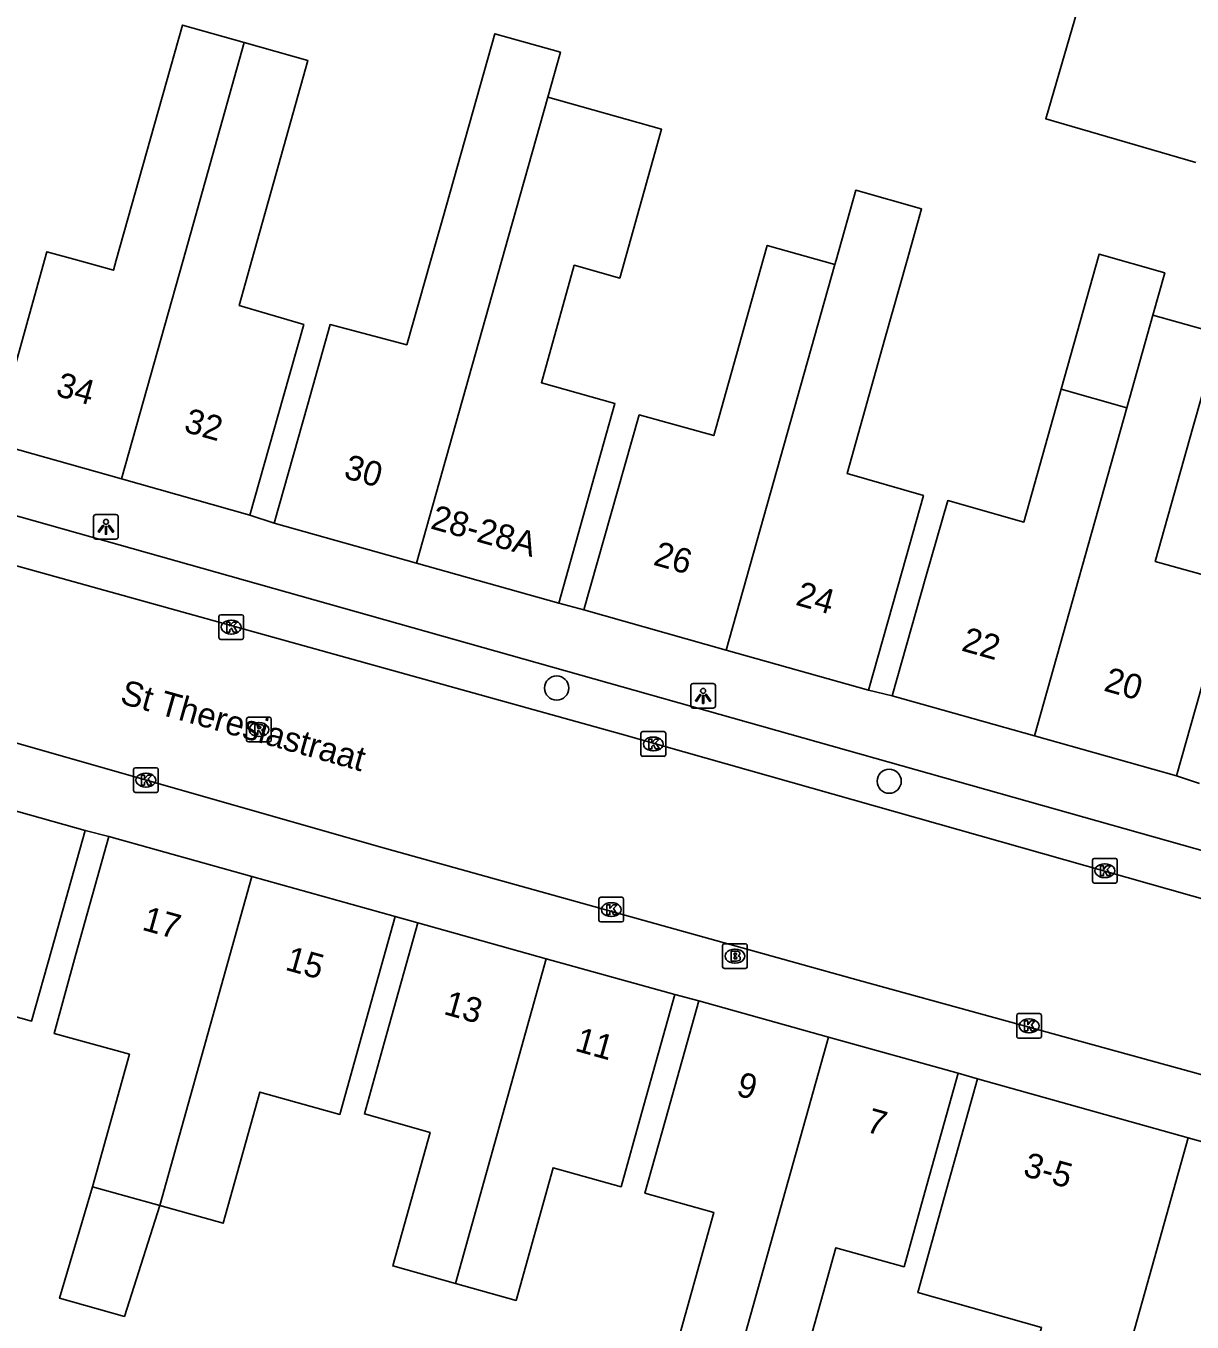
# Model space of a CAD drawing. Extents: x 158087 to 159494, y 382905 to 383981.
# Drawn here: x 158768.8 to 158816, y 383207 to 383259.5 of the extents above; entities that cross this region are included whole.
import ezdxf

# ---------------------------------------------------------------- set-up
doc = ezdxf.new("R2010")
doc.units = 0
for name, color, linetype in [('IMGEO_Boom', 7, 'Continuous'), ('IMGEO_Brandkraan', 7, 'Continuous'), ('IMGEO_Kolk', 7, 'Continuous'), ('IMGEO_Lichtpunt', 7, 'Continuous'), ('IMGEO_Openbare_ruimte_label', 7, 'Continuous'), ('IMGEO_Pand', 7, 'Continuous'), ('IMGEO_Pand_nummerreeks', 7, 'Continuous'), ('IMGEO_Rijbaan_lokaal_open', 7, 'Continuous'), ('IMGEO_Rioolput', 7, 'Continuous'), ('IMGEO_Voetpad_open', 7, 'Continuous')]:
    doc.layers.add(name, color=color, linetype=linetype)

msp = doc.modelspace()

# ---------------------------------------------------------------- linework, layer by layer
at = {"layer": 'IMGEO_Boom'}
for centre in [(158790.32, 383232.685), (158803.776, 383228.915)]:
    msp.add_circle(centre, 0.489, dxfattribs=at)
at = {"layer": 'IMGEO_Brandkraan'}
for p, q in [((158797.109, 383222.337), (158797.961, 383222.337)), ((158797.034, 383221.411), (158797.034, 383222.263)), ((158797.522, 383222.117), (158797.547, 383222.117)), ((158798.035, 383222.263), (158798.035, 383221.411)), ((158797.961, 383221.337), (158797.109, 383221.337)), ((158797.545, 383221.557), (158797.52, 383221.557))]:
    msp.add_line(p, q, dxfattribs=at)
for points in [[(158797.109, 383222.337), (158797.961, 383222.337)], [(158797.034, 383221.411), (158797.034, 383222.263)], [(158797.382, 383222.037), (158797.382, 383221.637), (158797.595, 383221.637)], [(158797.613, 383222.037), (158797.382, 383222.037)], [(158797.561, 383221.956), (158797.507, 383221.956), (158797.507, 383221.88)], [(158797.507, 383221.88), (158797.56, 383221.88)], [(158797.569, 383221.804), (158797.507, 383221.804), (158797.507, 383221.723)], [(158798.035, 383222.263), (158798.035, 383221.411)], [(158797.961, 383221.337), (158797.109, 383221.337)], [(158797.507, 383221.723), (158797.569, 383221.723)]]:
    msp.add_lwpolyline(points, dxfattribs=at)
for centre, radius, start, end in [((158797.111, 383222.261), 0.0765, 91.552, 178.448), ((158797.111, 383222.261), 0.0765, 91.552, 178.448), ((158797.959, 383222.261), 0.0765, 1.552, 88.448), ((158797.959, 383222.261), 0.0765, 1.552, 88.448), ((158797.562, 383221.918), 0.0379, 267.8285, 90.9355), ((158797.57, 383221.763), 0.0404, 269.8759, 90.5077), ((158797.617, 383221.892), 0.145, 59.4692, 91.5367), ((158797.642, 383221.939), 0.0922, 285.5137, 58.1501), ((158797.647, 383221.747), 0.105, 301.3115, 78.989), ((158797.111, 383221.413), 0.0765, 181.552, 268.448), ((158797.111, 383221.413), 0.0765, 181.552, 268.448), ((158797.601, 383221.888), 0.251, 268.6676, 293.5347), ((158797.959, 383221.413), 0.0765, 271.552, 358.448), ((158797.959, 383221.413), 0.0765, 271.552, 358.448)]:
    msp.add_arc(centre, radius, start, end, dxfattribs=at)
for centre, major_axis, ratio, start_param, end_param in [((158797.521, 383221.837), (-0.387, 0.002), 0.722429, 4.712389, 7.853982), ((158797.546, 383221.837), (-0.39, 0.002), 0.717154, 1.570796, 4.712389)]:
    msp.add_ellipse(centre, major_axis=major_axis, ratio=ratio, start_param=start_param, end_param=end_param, dxfattribs=at)
at = {"layer": 'IMGEO_Kolk'}
for p, q in [((158776.65, 383234.725), (158776.65, 383235.577)), ((158776.725, 383235.651), (158777.577, 383235.651)), ((158777.138, 383235.431), (158777.163, 383235.431)), ((158777.651, 383235.577), (158777.651, 383234.725)), ((158777.161, 383234.871), (158777.136, 383234.871)), ((158777.577, 383234.651), (158776.725, 383234.651)), ((158793.73, 383229.997), (158793.73, 383230.849)), ((158793.805, 383230.923), (158794.657, 383230.923)), ((158794.218, 383230.703), (158794.243, 383230.703)), ((158794.731, 383230.849), (158794.731, 383229.997)), ((158794.241, 383230.143), (158794.216, 383230.143)), ((158794.657, 383229.923), (158793.805, 383229.923)), ((158773.196, 383228.535), (158773.196, 383229.387)), ((158773.271, 383229.461), (158774.123, 383229.461)), ((158773.684, 383229.241), (158773.709, 383229.241)), ((158774.197, 383229.387), (158774.197, 383228.535)), ((158773.707, 383228.681), (158773.682, 383228.681)), ((158774.123, 383228.461), (158773.271, 383228.461)), ((158812.002, 383224.868), (158812.002, 383225.72)), ((158812.077, 383225.794), (158812.929, 383225.794)), ((158812.49, 383225.574), (158812.515, 383225.574)), ((158813.003, 383225.72), (158813.003, 383224.868)), ((158812.513, 383225.014), (158812.488, 383225.014)), ((158812.929, 383224.794), (158812.077, 383224.794)), ((158792.029, 383223.294), (158792.029, 383224.146)), ((158792.104, 383224.22), (158792.956, 383224.22)), ((158792.517, 383224), (158792.542, 383224)), ((158793.03, 383224.146), (158793.03, 383223.294)), ((158792.54, 383223.44), (158792.515, 383223.44)), ((158792.956, 383223.22), (158792.104, 383223.22)), ((158808.937, 383218.589), (158808.937, 383219.441)), ((158809.012, 383219.515), (158809.864, 383219.515)), ((158809.425, 383219.295), (158809.45, 383219.295)), ((158809.938, 383219.441), (158809.938, 383218.589)), ((158809.448, 383218.735), (158809.423, 383218.735)), ((158809.864, 383218.515), (158809.012, 383218.515))]:
    msp.add_line(p, q, dxfattribs=at)
for points in [[(158776.65, 383234.725), (158776.65, 383235.577)], [(158776.725, 383235.651), (158777.577, 383235.651)], [(158777.651, 383235.577), (158777.651, 383234.725)], [(158776.971, 383235.351), (158777.094, 383235.351), (158777.094, 383235.2), (158777.224, 383235.351), (158777.388, 383235.351), (158777.242, 383235.2), (158777.395, 383234.951), (158777.243, 383234.951), (158777.158, 383235.115), (158777.094, 383235.048), (158777.094, 383234.951), (158776.971, 383234.951), (158776.971, 383235.351)], [(158777.577, 383234.651), (158776.725, 383234.651)], [(158793.73, 383229.997), (158793.73, 383230.849)], [(158793.805, 383230.923), (158794.657, 383230.923)], [(158794.731, 383230.849), (158794.731, 383229.997)], [(158794.051, 383230.623), (158794.174, 383230.623), (158794.174, 383230.472), (158794.304, 383230.623), (158794.468, 383230.623), (158794.322, 383230.472), (158794.475, 383230.223), (158794.323, 383230.223), (158794.238, 383230.387), (158794.174, 383230.32), (158794.174, 383230.223), (158794.051, 383230.223), (158794.051, 383230.623)], [(158794.657, 383229.923), (158793.805, 383229.923)], [(158773.196, 383228.535), (158773.196, 383229.387)], [(158773.271, 383229.461), (158774.123, 383229.461)], [(158773.517, 383229.161), (158773.64, 383229.161), (158773.64, 383229.01), (158773.77, 383229.161), (158773.934, 383229.161), (158773.788, 383229.01), (158773.941, 383228.761), (158773.789, 383228.761), (158773.704, 383228.925), (158773.64, 383228.858), (158773.64, 383228.761), (158773.517, 383228.761), (158773.517, 383229.161)], [(158774.197, 383229.387), (158774.197, 383228.535)], [(158774.123, 383228.461), (158773.271, 383228.461)], [(158812.002, 383224.868), (158812.002, 383225.72)], [(158812.077, 383225.794), (158812.929, 383225.794)], [(158812.323, 383225.494), (158812.446, 383225.494), (158812.446, 383225.343), (158812.576, 383225.494), (158812.74, 383225.494), (158812.594, 383225.343), (158812.747, 383225.094), (158812.595, 383225.094), (158812.51, 383225.258), (158812.446, 383225.191), (158812.446, 383225.094), (158812.323, 383225.094), (158812.323, 383225.494)], [(158813.003, 383225.72), (158813.003, 383224.868)], [(158812.929, 383224.794), (158812.077, 383224.794)], [(158792.029, 383223.294), (158792.029, 383224.146)], [(158792.104, 383224.22), (158792.956, 383224.22)], [(158792.35, 383223.92), (158792.473, 383223.92), (158792.473, 383223.769), (158792.603, 383223.92), (158792.767, 383223.92), (158792.621, 383223.769), (158792.774, 383223.52), (158792.622, 383223.52), (158792.537, 383223.684), (158792.473, 383223.617), (158792.473, 383223.52), (158792.35, 383223.52), (158792.35, 383223.92)], [(158793.03, 383224.146), (158793.03, 383223.294)], [(158792.956, 383223.22), (158792.104, 383223.22)], [(158808.937, 383218.589), (158808.937, 383219.441)], [(158809.012, 383219.515), (158809.864, 383219.515)], [(158809.258, 383219.215), (158809.381, 383219.215), (158809.381, 383219.064), (158809.511, 383219.215), (158809.675, 383219.215), (158809.529, 383219.064), (158809.682, 383218.815), (158809.53, 383218.815), (158809.445, 383218.979), (158809.381, 383218.912), (158809.381, 383218.815), (158809.258, 383218.815), (158809.258, 383219.215)], [(158809.938, 383219.441), (158809.938, 383218.589)], [(158809.864, 383218.515), (158809.012, 383218.515)]]:
    msp.add_lwpolyline(points, dxfattribs=at)
for centre, start, end in [((158776.727, 383235.575), 91.552, 178.448), ((158776.727, 383235.575), 91.552, 178.448), ((158777.575, 383235.575), 1.552, 88.448), ((158777.575, 383235.575), 1.552, 88.448), ((158776.727, 383234.727), 181.552, 268.448), ((158776.727, 383234.727), 181.552, 268.448), ((158777.575, 383234.727), 271.552, 358.448), ((158777.575, 383234.727), 271.552, 358.448), ((158793.807, 383230.847), 91.552, 178.448), ((158793.807, 383230.847), 91.552, 178.448), ((158794.655, 383230.847), 1.552, 88.448), ((158794.655, 383230.847), 1.552, 88.448), ((158793.807, 383229.999), 181.552, 268.448), ((158793.807, 383229.999), 181.552, 268.448), ((158794.655, 383229.999), 271.552, 358.448), ((158794.655, 383229.999), 271.552, 358.448), ((158773.273, 383229.385), 91.552, 178.448), ((158773.273, 383229.385), 91.552, 178.448), ((158774.121, 383229.385), 1.552, 88.448), ((158774.121, 383229.385), 1.552, 88.448), ((158773.273, 383228.537), 181.552, 268.448), ((158773.273, 383228.537), 181.552, 268.448), ((158774.121, 383228.537), 271.552, 358.448), ((158774.121, 383228.537), 271.552, 358.448), ((158812.079, 383225.718), 91.552, 178.448), ((158812.079, 383225.718), 91.552, 178.448), ((158812.927, 383225.718), 1.552, 88.448), ((158812.927, 383225.718), 1.552, 88.448), ((158812.079, 383224.87), 181.552, 268.448), ((158812.079, 383224.87), 181.552, 268.448), ((158812.927, 383224.87), 271.552, 358.448), ((158812.927, 383224.87), 271.552, 358.448), ((158792.106, 383224.144), 91.552, 178.448), ((158792.106, 383224.144), 91.552, 178.448), ((158792.954, 383224.144), 1.552, 88.448), ((158792.954, 383224.144), 1.552, 88.448), ((158792.106, 383223.296), 181.552, 268.448), ((158792.106, 383223.296), 181.552, 268.448), ((158792.954, 383223.296), 271.552, 358.448), ((158792.954, 383223.296), 271.552, 358.448), ((158809.014, 383219.439), 91.552, 178.448), ((158809.014, 383219.439), 91.552, 178.448), ((158809.862, 383219.439), 1.552, 88.448), ((158809.862, 383219.439), 1.552, 88.448), ((158809.014, 383218.591), 181.552, 268.448), ((158809.014, 383218.591), 181.552, 268.448), ((158809.862, 383218.591), 271.552, 358.448), ((158809.862, 383218.591), 271.552, 358.448)]:
    msp.add_arc(centre, 0.0765, start, end, dxfattribs=at)
for centre, major_axis, ratio, start_param, end_param in [((158777.137, 383235.151), (-0.387, 0.002), 0.722429, 4.712389, 7.853982), ((158777.162, 383235.151), (-0.39, 0.002), 0.717154, 1.570796, 4.712389), ((158794.217, 383230.423), (-0.387, 0.002), 0.722429, 4.712389, 7.853982), ((158794.242, 383230.423), (-0.39, 0.002), 0.717154, 1.570796, 4.712389), ((158773.683, 383228.961), (-0.387, 0.002), 0.722429, 4.712389, 7.853982), ((158773.708, 383228.961), (-0.39, 0.002), 0.717154, 1.570796, 4.712389), ((158812.489, 383225.294), (-0.387, 0.002), 0.722429, 4.712389, 7.853982), ((158812.514, 383225.294), (-0.39, 0.002), 0.717154, 1.570796, 4.712389), ((158792.516, 383223.72), (-0.387, 0.002), 0.722429, 4.712389, 7.853982), ((158792.541, 383223.72), (-0.39, 0.002), 0.717154, 1.570796, 4.712389), ((158809.424, 383219.015), (-0.387, 0.002), 0.722429, 4.712389, 7.853982), ((158809.449, 383219.015), (-0.39, 0.002), 0.717154, 1.570796, 4.712389)]:
    msp.add_ellipse(centre, major_axis=major_axis, ratio=ratio, start_param=start_param, end_param=end_param, dxfattribs=at)
at = {"layer": 'IMGEO_Lichtpunt'}
for p, q in [((158771.583, 383239.613), (158771.583, 383238.806)), ((158771.583, 383239.613), (158771.583, 383238.806)), ((158772.485, 383239.708), (158771.677, 383239.708)), ((158772.485, 383239.708), (158771.677, 383239.708)), ((158772.579, 383238.806), (158772.579, 383239.613)), ((158772.579, 383238.806), (158772.579, 383239.613)), ((158771.677, 383238.712), (158772.485, 383238.712)), ((158771.677, 383238.712), (158772.485, 383238.712)), ((158795.747, 383232.773), (158795.747, 383231.966)), ((158795.747, 383232.773), (158795.747, 383231.966)), ((158796.649, 383232.868), (158795.841, 383232.868)), ((158796.649, 383232.868), (158795.841, 383232.868)), ((158796.743, 383231.966), (158796.743, 383232.773)), ((158796.743, 383231.966), (158796.743, 383232.773)), ((158795.841, 383231.872), (158796.649, 383231.872)), ((158795.841, 383231.872), (158796.649, 383231.872))]:
    msp.add_line(p, q, dxfattribs=at)
for points in [[(158771.957, 383239.277), (158771.996, 383239.249), (158771.808, 383238.987), (158771.77, 383239.014), (158771.957, 383239.277)], [(158772.059, 383239.229), (158772.106, 383239.229), (158772.106, 383238.907), (158772.059, 383238.907), (158772.059, 383239.229)], [(158772.169, 383239.249), (158772.207, 383239.276), (158772.394, 383239.014), (158772.355, 383238.986), (158772.169, 383239.249)], [(158796.121, 383232.437), (158796.16, 383232.409), (158795.972, 383232.147), (158795.934, 383232.174), (158796.121, 383232.437)], [(158796.223, 383232.389), (158796.27, 383232.389), (158796.27, 383232.067), (158796.223, 383232.067), (158796.223, 383232.389)], [(158796.333, 383232.409), (158796.371, 383232.436), (158796.558, 383232.174), (158796.519, 383232.146), (158796.333, 383232.409)]]:
    msp.add_lwpolyline(points, dxfattribs=at)
for centre in [(158772.082, 383239.411), (158796.246, 383232.571)]:
    msp.add_circle(centre, 0.0994, dxfattribs=at)
for centre, start, end in [((158771.677, 383239.613), 90, 180), ((158771.677, 383239.613), 90, 180), ((158772.485, 383239.613), 0, 90), ((158772.485, 383239.613), 0, 90), ((158771.677, 383238.806), 180, 270), ((158771.677, 383238.806), 180, 270), ((158772.485, 383238.806), 270, 0), ((158772.485, 383238.806), 270, 360), ((158795.841, 383232.773), 90, 180), ((158795.841, 383232.773), 90, 180), ((158796.649, 383232.773), 0, 90), ((158796.649, 383232.773), 0, 90), ((158795.841, 383231.966), 180, 270), ((158795.841, 383231.966), 180, 270), ((158796.649, 383231.966), 270, 0), ((158796.649, 383231.966), 270, 360)]:
    msp.add_arc(centre, 0.0946, start, end, dxfattribs=at)
at = {"layer": 'IMGEO_Pand'}
for points in [[(158816.186, 383253.951), (158810.112, 383255.724), (158811.724, 383261.246), (158817.797, 383259.473)], [(158767.525, 383242.607), (158768.878, 383247.421), (158769.595, 383250), (158769.691, 383250.344), (158770.925, 383250), (158772.384, 383249.593), (158772.499, 383250), (158773.886, 383254.929), (158775.176, 383259.514), (158777.675, 383258.811)], [(158778.893, 383239.358), (158780.247, 383244.172), (158781.153, 383247.395), (158784.254, 383246.576), (158785.228, 383250), (158785.711, 383251.699), (158787.812, 383259.161), (158790.469, 383258.413), (158789.958, 383256.596)], [(158777.675, 383258.811), (158776.389, 383254.231), (158775.201, 383250), (158772.715, 383241.148)], [(158777.675, 383258.811), (158780.252, 383258.086), (158778.965, 383253.512), (158777.986, 383250), (158777.474, 383248.161), (158780.088, 383247.403), (158779.26, 383244.502), (158777.906, 383239.688)], [(158784.65, 383237.74), (158788.101, 383250), (158788.37, 383250.955), (158789.958, 383256.596)], [(158789.958, 383256.596), (158794.566, 383255.299), (158792.87, 383249.277), (158791.034, 383249.792), (158789.701, 383245.038), (158792.678, 383244.196), (158791.761, 383240.935), (158790.407, 383236.121)], [(158801.575, 383249.827), (158801.624, 383250), (158802.421, 383252.831), (158805.087, 383252.08), (158804.501, 383250), (158803.604, 383246.815), (158802.069, 383241.366), (158805.163, 383240.472), (158804.297, 383237.413), (158802.942, 383232.6)], [(158791.421, 383235.845), (158792.777, 383240.658), (158793.665, 383243.736), (158796.677, 383242.903), (158798.207, 383248.335), (158798.844, 383250.597), (158801.575, 383249.827)], [(158814.447, 383247.777), (158814.929, 383249.489), (158812.273, 383250.237), (158810.734, 383244.774)], [(158797.18, 383234.223), (158801.575, 383249.827)], [(158813.391, 383244.026), (158814.447, 383247.777)], [(158814.447, 383247.777), (158817.137, 383247.02), (158816.081, 383243.268), (158814.543, 383237.804), (158817.601, 383236.956), (158816.759, 383233.943), (158815.403, 383229.13)], [(158803.899, 383232.37), (158805.255, 383237.183), (158806.144, 383240.275), (158809.22, 383239.399), (158810.734, 383244.774)], [(158810.734, 383244.774), (158813.391, 383244.026)], [(158813.391, 383244.026), (158809.652, 383230.75)], [(158772.715, 383241.148), (158767.525, 383242.607)], [(158777.906, 383239.688), (158772.715, 383241.148)], [(158784.65, 383237.74), (158778.893, 383239.358)], [(158790.407, 383236.121), (158784.65, 383237.74)], [(158797.18, 383234.223), (158791.421, 383235.845)], [(158802.942, 383232.6), (158797.18, 383234.223)], [(158809.652, 383230.75), (158803.899, 383232.37)], [(158815.403, 383229.13), (158809.652, 383230.75)], [(158765.426, 383228.551), (158771.237, 383226.928)], [(158761.925, 383216.019), (158764.141, 383215.4), (158764.758, 383217.611), (158765.312, 383217.456), (158766.039, 383220.059), (158769.07, 383219.211), (158769.893, 383222.113), (158771.237, 383226.928)], [(158772.192, 383226.683), (158770.847, 383221.868), (158769.979, 383218.702), (158773.033, 383217.868), (158771.535, 383212.507)], [(158772.192, 383226.683), (158777.985, 383225.064)], [(158774.262, 383211.745), (158777.985, 383225.064)], [(158777.985, 383225.064), (158783.781, 383223.445)], [(158774.262, 383211.745), (158776.821, 383211.03), (158778.304, 383216.338), (158781.543, 383215.434), (158782.436, 383218.63), (158783.781, 383223.445)], [(158784.697, 383223.187), (158783.352, 383218.372), (158782.54, 383215.45), (158785.199, 383214.696), (158783.689, 383209.301), (158786.225, 383208.593)], [(158789.896, 383221.735), (158784.697, 383223.187)], [(158786.225, 383208.593), (158789.896, 383221.735)], [(158789.896, 383221.735), (158795.097, 383220.282)], [(158786.225, 383208.593), (158788.675, 383207.908), (158790.174, 383213.273), (158792.924, 383212.505), (158793.752, 383215.467), (158795.097, 383220.282)], [(158796.067, 383220.029), (158794.722, 383215.214), (158793.893, 383212.249), (158796.684, 383211.469), (158795.199, 383206.154), (158797.655, 383205.469)], [(158796.067, 383220.029), (158801.315, 383218.563)], [(158801.315, 383218.563), (158797.655, 383205.469)], [(158806.567, 383217.096), (158801.315, 383218.563)], [(158799.874, 383204.849), (158800.143, 383204.774), (158801.614, 383210.039), (158804.38, 383209.267), (158805.222, 383212.281), (158806.567, 383217.096)], [(158807.354, 383216.868), (158806.005, 383212.054), (158804.931, 383208.22), (158809.944, 383206.815), (158808.551, 383201.842), (158811.426, 383201.036)], [(158807.354, 383216.868), (158815.88, 383214.479)], [(158815.88, 383214.479), (158812.062, 383200.858), (158811.426, 383201.036)], [(158834.144, 383209.36), (158815.88, 383214.479)], [(158771.535, 383212.507), (158770.206, 383207.992), (158772.829, 383207.259), (158774.262, 383211.745)], [(158774.262, 383211.745), (158771.535, 383212.507)]]:
    msp.add_lwpolyline(points, dxfattribs=at)
at = {"layer": 'IMGEO_Rijbaan_lokaal_open'}
for points in [[(158766.515, 383238.164), (158767.383, 383237.924), (158792.938, 383230.817), (158816.826, 383224.045), (158825.794, 383221.597)], [(158823.947, 383214.968), (158802.524, 383220.86), (158783.113, 383226.274), (158766.719, 383230.948), (158764.65, 383231.517)]]:
    msp.add_lwpolyline(points, dxfattribs=at)
at = {"layer": 'IMGEO_Rioolput'}
for p, q in [((158777.772, 383230.581), (158777.772, 383231.433)), ((158777.847, 383231.507), (158778.699, 383231.507)), ((158778.26, 383231.287), (158778.285, 383231.287)), ((158778.773, 383231.433), (158778.773, 383230.581)), ((158778.283, 383230.727), (158778.258, 383230.727)), ((158778.699, 383230.507), (158777.847, 383230.507))]:
    msp.add_line(p, q, dxfattribs=at)
for points in [[(158777.772, 383230.581), (158777.772, 383231.433)], [(158777.847, 383231.507), (158778.699, 383231.507)], [(158778.361, 383231.205), (158778.109, 383231.207), (158778.109, 383230.807)], [(158778.773, 383231.433), (158778.773, 383230.581)], [(158778.109, 383230.807), (158778.233, 383230.807), (158778.233, 383230.969), (158778.244, 383230.969)], [(158778.287, 383231.126), (158778.233, 383231.126), (158778.233, 383231.045)], [(158778.233, 383231.045), (158778.285, 383231.045)], [(158778.291, 383230.94), (158778.362, 383230.807), (158778.502, 383230.807), (158778.437, 383230.933)], [(158778.699, 383230.507), (158777.847, 383230.507)]]:
    msp.add_lwpolyline(points, dxfattribs=at)
for centre, radius, start, end in [((158777.849, 383231.431), 0.0765, 91.552, 178.448), ((158777.849, 383231.431), 0.0765, 91.552, 178.448), ((158778.36, 383231.095), 0.109, 350.3612, 89.416), ((158778.697, 383231.431), 0.0765, 1.552, 88.448), ((158778.697, 383231.431), 0.0765, 1.552, 88.448), ((158778.243, 383230.916), 0.0533, 26.0293, 88.6989), ((158778.269, 383231.234), 0.19, 274.7715, 282.9687), ((158778.293, 383231.03), 0.0964, 77.0061, 93.1865), ((158778.307, 383231.087), 0.0378, 276.6634, 79.6772), ((158778.358, 383231.095), 0.112, 277.5842, 350.9817), ((158778.342, 383230.88), 0.108, 29.5134, 73.7905), ((158777.849, 383230.583), 0.0765, 181.552, 268.448), ((158777.849, 383230.583), 0.0765, 181.552, 268.448), ((158778.697, 383230.583), 0.0765, 271.552, 358.448), ((158778.697, 383230.583), 0.0765, 271.552, 358.448)]:
    msp.add_arc(centre, radius, start, end, dxfattribs=at)
for centre, major_axis, ratio, start_param, end_param in [((158778.259, 383231.007), (-0.387, 0.002), 0.722429, 4.712389, 7.853982), ((158778.284, 383231.007), (-0.39, 0.002), 0.717154, 1.570796, 4.712389)]:
    msp.add_ellipse(centre, major_axis=major_axis, ratio=ratio, start_param=start_param, end_param=end_param, dxfattribs=at)
at = {"layer": 'IMGEO_Voetpad_open'}
for points in [[(158736.759, 383248.525), (158751.096, 383244.547), (158852.366, 383215.967)], [(158777.906, 383239.688), (158778.893, 383239.358)], [(158790.407, 383236.121), (158791.421, 383235.845)], [(158802.942, 383232.6), (158803.899, 383232.37)], [(158815.403, 383229.13), (158816.339, 383228.827)], [(158771.237, 383226.928), (158772.192, 383226.683)], [(158783.781, 383223.445), (158784.697, 383223.187)], [(158795.097, 383220.282), (158796.067, 383220.029)], [(158806.567, 383217.096), (158807.354, 383216.868)]]:
    msp.add_lwpolyline(points, dxfattribs=at)

# ---------------------------------------------------------------- texts
at = {"layer": 'IMGEO_Openbare_ruimte_label'}
msp.add_text('St Theresiastraat', height=1, rotation=344.2121, dxfattribs=at).set_placement((158772.608, 383232.079))
at = {"layer": 'IMGEO_Pand_nummerreeks'}
for s, rotation, p in [('34', 344.2947, (158770.007, 383244.527)), ('32', 344.2947, (158775.195, 383243.068)), ('30', 344.2974, (158781.661, 383241.198)), ('28-28A', 344.2952, (158785.174, 383239.151)), ('26', 344.2696, (158794.189, 383237.683)), ('24', 344.2696, (158799.95, 383236.061)), ('22', 344.2706, (158806.66, 383234.21)), ('20', 344.2706, (158812.418, 383232.588)), ('17', 344.3895, (158773.499, 383222.912)), ('15', 344.3895, (158779.293, 383221.293)), ('13', 344.3926, (158785.707, 383219.5)), ('11', 344.3935, (158791.017, 383218.017)), ('9', 344.3932, (158797.545, 383216.211)), ('7', 344.3926, (158802.794, 383214.744)), ('3-5', 344.347, (158809.151, 383212.958))]:
    msp.add_text(s, height=1, rotation=rotation, dxfattribs=at).set_placement(p)

doc.saveas('drawing.dxf')
